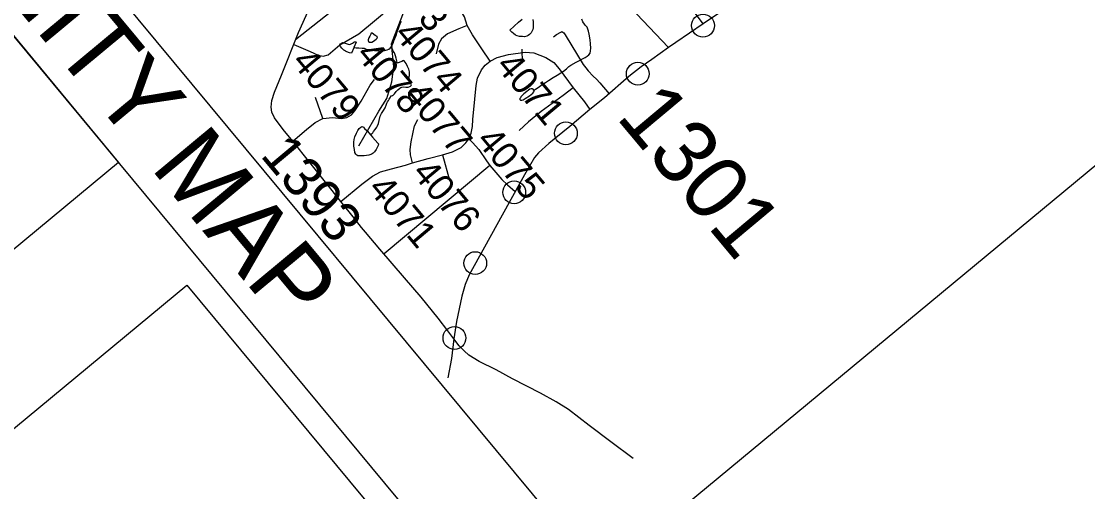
# Model space of a CAD drawing. Extents: x 2054826 to 2060231, y 685508 to 690809.
# Drawn here: x 2058521.5 to 2058951.1, y 689254.7 to 689444.4 of the extents above; entities that cross this region are included whole.
import ezdxf

# ---------------------------------------------------------------- set-up
doc = ezdxf.new("R2010")
doc.units = 0
for name, color, linetype in [('Default', 7, 'Continuous'), ('Old_Level_11', 7, 'Continuous'), ('Old_Level_21', 7, 'Continuous'), ('Old_Level_32', 7, 'Continuous'), ('Old_Level_35', 7, 'Continuous'), ('Old_Level_59', 7, 'Continuous'), ('Old_Level_62', 7, 'Continuous'), ('Old_Level_8', 7, 'Continuous')]:
    doc.layers.add(name, color=color, linetype=linetype)

msp = doc.modelspace()

# ---------------------------------------------------------------- linework, layer by layer
at = {"layer": 'Default'}
for p, q in [((2058363.32, 689625.52), (2058560.72, 689387.48)), ((2058560.72, 689387.48), (2058500.46, 689337.51))]:
    msp.add_line(p, q, dxfattribs=at)
msp.add_lwpolyline([(2058776.37, 689968.05), (2059134.67, 689535.97), (2058721.62, 689193.45), (2058363.32, 689625.52)], close=True, dxfattribs=at)
for centre in [(2058796.12, 689442.62), (2058769.86, 689423.23), (2058740.89, 689399.2), (2058720.08, 689375.4), (2058704.38, 689346.88), (2058696.01, 689316.7)]:
    msp.add_circle(centre, 4.59, dxfattribs=at)
at = {"layer": 'Old_Level_21'}
msp.add_line((2058396.35, 689652.92), (2058754.65, 689220.85), dxfattribs=at)
msp.add_lwpolyline([(2058588.27, 689338), (2059498.4, 688240.46), (2058988.43, 687817.56), (2058078.29, 688915.11)], close=True, dxfattribs=at)
at = {"layer": 'Old_Level_32'}
for p, q in [((2058642.98, 689405.21), (2058640.1, 689413.7)), ((2058691.15, 689390.54), (2058694, 689380.33))]:
    msp.add_line(p, q, dxfattribs=at)
for points in [[(2058623.47, 689405.45), (2058622.51, 689407.72), (2058622.25, 689409.71), (2058622.42, 689412.39), (2058623.56, 689415.82), (2058626.32, 689422.6), (2058633.19, 689439.78), (2058639.88, 689454.86), (2058642.73, 689462.33), (2058644.57, 689467.01), (2058645.65, 689471.4), (2058646.84, 689478.34), (2058647.37, 689483.86), (2058648.12, 689488.16), (2058649.2, 689492.55), (2058653.05, 689504.79), (2058654.38, 689509.38)], [(2058782.21, 689433.75), (2058764.28, 689452.71), (2058757.84, 689460.49), (2058755.43, 689463.58), (2058754.43, 689465.56), (2058753.73, 689467.78), (2058753.31, 689471.05), (2058753.55, 689473.72), (2058754.46, 689476.97), (2058756.27, 689481.12), (2058757.78, 689484.85), (2058758.53, 689487.3), (2058758.67, 689489.22), (2058758.52, 689491.56), (2058757.42, 689494.61), (2058756.92, 689495.64)], [(2058796.17, 689443.35), (2058793.53, 689447.03), (2058791.73, 689449.27), (2058788.76, 689451.86), (2058785.36, 689454.57), (2058782.34, 689457.46), (2058779.99, 689460.51), (2058778.6, 689464.44), (2058777.91, 689469.35), (2058777.15, 689476.78)], [(2058825.7, 689475.43), (2058824.91, 689472.75), (2058823.36, 689467.6), (2058821.22, 689463.57), (2058818.07, 689459.37), (2058815.24, 689456.59), (2058810.85, 689453.12), (2058805.32, 689449.45), (2058799.91, 689445.85), (2058796.17, 689443.35)], [(2058701.16, 689442.68), (2058700.09, 689446.13), (2058698.89, 689448.2), (2058697.15, 689449.48), (2058694.2, 689451.16), (2058691.65, 689453.09), (2058687.93, 689457.27)], [(2058701.16, 689442.68), (2058697.78, 689441.29), (2058693.23, 689439.32), (2058690.78, 689437.29), (2058689.61, 689435.1), (2058688.65, 689431.29)], [(2058710.41, 689428.35), (2058707.02, 689433.27), (2058703.34, 689438.88), (2058701.16, 689442.68)], [(2058796.17, 689443.35), (2058785.21, 689435.86), (2058782.21, 689433.75)], [(2058782.21, 689433.75), (2058775.48, 689429.02), (2058771.23, 689425.94), (2058766.23, 689422.08), (2058756.44, 689413.47), (2058750.56, 689408.82)], [(2058710.41, 689428.35), (2058713.27, 689429.72), (2058717.79, 689430.96), (2058724.44, 689431.97), (2058728, 689431.6), (2058732.84, 689429.76), (2058736.06, 689427.71), (2058738.2, 689425.15), (2058743.86, 689417.59)], [(2058701.83, 689396.92), (2058702.7, 689399.33), (2058703.29, 689401.94), (2058703.48, 689404.84), (2058704.25, 689412.95), (2058704.73, 689418.46), (2058705.31, 689421.49), (2058706.85, 689424.84), (2058708.4, 689426.63), (2058710.41, 689428.35)], [(2058642.98, 689405.21), (2058646.87, 689405.53), (2058650.46, 689405.15), (2058652.72, 689405.57), (2058654.52, 689406.61), (2058655.91, 689408.31), (2058658.37, 689412.17), (2058662.03, 689418.67), (2058663.83, 689420.85)], [(2058743.86, 689417.59), (2058739.86, 689414.42), (2058730.99, 689407.98), (2058725.88, 689403.89), (2058722.12, 689400.39)], [(2058743.86, 689417.59), (2058748.33, 689411.85), (2058750.56, 689408.82)], [(2058750.56, 689408.82), (2058742.49, 689401.99), (2058734.05, 689395.04), (2058729.86, 689391.33), (2058728.2, 689389.48), (2058724.17, 689382.46), (2058718.11, 689371.38), (2058708.07, 689353.31), (2058701.98, 689342.11), (2058700.29, 689338.22), (2058698.93, 689333.6), (2058696.83, 689323.32), (2058695.8, 689316.39)], [(2058630.92, 689396.1), (2058627.08, 689400.77), (2058623.47, 689405.45)], [(2058630.92, 689396.1), (2058636.35, 689400.74), (2058639.92, 689403.52), (2058642.98, 689405.21)], [(2058679.14, 689387.27), (2058678.34, 689390.54), (2058678.17, 689392.74), (2058678.58, 689395.76), (2058679.92, 689402.25), (2058681.3, 689404.8)], [(2058650.29, 689371.78), (2058646.23, 689376.88), (2058637.76, 689387.44), (2058630.92, 689396.1)], [(2058691.15, 689390.54), (2058695.23, 689391.78), (2058698.67, 689393.54), (2058700.62, 689395.41), (2058701.83, 689396.92)], [(2058701.83, 689396.92), (2058703.29, 689395.54), (2058705.8, 689392.66), (2058708.93, 689388.12), (2058710.33, 689386.19)], [(2058679.14, 689387.27), (2058685.42, 689389.08), (2058691.15, 689390.54)], [(2058650.29, 689371.78), (2058658.66, 689378.71), (2058663.02, 689381.89), (2058666.27, 689383.61), (2058670.67, 689384.87), (2058676.33, 689386.39), (2058679.14, 689387.27)], [(2058660.24, 689359.38), (2058658.61, 689361.22), (2058655.69, 689364.93), (2058650.29, 689371.78)], [(2058695.8, 689316.39), (2058693.29, 689319.6), (2058689.4, 689324.74), (2058682.54, 689333.11), (2058675.87, 689340.96), (2058666.01, 689352.51), (2058660.24, 689359.38)], [(2058695.8, 689316.39), (2058694.8, 689308.46), (2058693.34, 689300.63)], [(2058741.98, 689287.86), (2058736.93, 689291.02), (2058730.64, 689294.52), (2058719.36, 689300.26), (2058712.8, 689303.86), (2058705.97, 689307.24), (2058701.86, 689309.82), (2058699.88, 689311.48), (2058697.94, 689313.56), (2058695.8, 689316.39)], [(2058767.94, 689268.1), (2058758.97, 689274.86), (2058750.24, 689281.46), (2058741.98, 689287.86)]]:
    msp.add_lwpolyline(points, dxfattribs=at)
at = {"layer": 'Old_Level_35'}
for p, q in [((2058668.48, 689465.84), (2058632.05, 689436.93)), ((2058723.19, 689433.13), (2058723.23, 689427.78)), ((2058710.33, 689386.19), (2058667.66, 689350.58))]:
    msp.add_line(p, q, dxfattribs=at)
for points in [[(2058631.3, 689435.05), (2058637.84, 689432.16), (2058641.06, 689430.76), (2058643.15, 689430.28), (2058645.17, 689430.88), (2058649.86, 689434.93), (2058657.5, 689439.33), (2058670.89, 689450.41)], [(2058735.91, 689438.13), (2058737.17, 689439.05), (2058738.8, 689440.03), (2058739.24, 689440.21), (2058739.73, 689440.02), (2058740.02, 689439.76), (2058740.58, 689438.96), (2058747.9, 689426.92), (2058748.91, 689425.56), (2058749.89, 689424.35), (2058751.92, 689422.23), (2058753.22, 689421.02), (2058754.59, 689419.62), (2058758.35, 689415.15)], [(2058710.33, 689386.19), (2058715.15, 689380.54), (2058717.32, 689378.4), (2058720.5, 689375.75)]]:
    msp.add_lwpolyline(points, dxfattribs=at)
at = {"layer": 'Old_Level_59'}
msp.add_lwpolyline([(2058657.45, 689394.18), (2058665.56, 689408.08), (2058668.72, 689413.18), (2058670.84, 689419.9), (2058671.54, 689426.18), (2058670.65, 689435.3), (2058675.87, 689448.9), (2058677.76, 689461.15)], dxfattribs=at)
at = {"layer": 'Old_Level_62'}
for points in [[(2058670.84, 689434.29), (2058670.89, 689434.43), (2058670.97, 689434.75), (2058671.26, 689435.5), (2058671.63, 689436.47), (2058671.99, 689437.37), (2058672.44, 689438.35), (2058672.72, 689439.01), (2058672.74, 689439.71), (2058672.87, 689440.16), (2058673.06, 689440.55), (2058673.16, 689440.83), (2058673.49, 689441.44), (2058673.7, 689442.21), (2058674.11, 689443.33), (2058674.63, 689444.44)], [(2058727.59, 689445.03), (2058727.71, 689444.18), (2058727.69, 689442.98), (2058727.68, 689441.79), (2058727.53, 689441.06), (2058727.23, 689440.31), (2058726.9, 689439.69), (2058726.25, 689439.06), (2058725.71, 689438.69), (2058725.12, 689438.38), (2058724.27, 689438.16), (2058723.4, 689438.19), (2058722.25, 689438.26), (2058721.21, 689438.48), (2058720.58, 689438.81), (2058719.76, 689439.39), (2058719.09, 689440), (2058718.7, 689440.36), (2058718.36, 689440.76), (2058721.87, 689443.96), (2058723.31, 689445.17)], [(2058728.01, 689416.63), (2058728.32, 689416.78), (2058728.65, 689416.98), (2058729.34, 689417.38), (2058730.31, 689418.04), (2058731.4, 689418.86), (2058732.62, 689419.64), (2058733.88, 689420.45), (2058735.71, 689421.71), (2058737.41, 689422.71), (2058738.86, 689423.52), (2058739.94, 689424.25), (2058741.13, 689425.26), (2058741.75, 689425.85), (2058742.04, 689426.1), (2058742.87, 689426.64), (2058745, 689427.83), (2058746.6, 689428.65), (2058747.61, 689429.17), (2058748.68, 689429.72), (2058749.51, 689430.25), (2058750.2, 689430.84), (2058750.63, 689431.53), (2058750.84, 689432.4), (2058750.93, 689433.49), (2058750.81, 689435.26), (2058750.63, 689436.89), (2058750.27, 689439.12), (2058750.01, 689440.35), (2058749.76, 689441.15), (2058749.41, 689441.97), (2058748.79, 689442.71), (2058748.33, 689443.17), (2058747.72, 689444.1), (2058747.27, 689445.25)], [(2058664.12, 689438.67), (2058662.82, 689439.61), (2058662.52, 689439.54), (2058662.31, 689439.18), (2058661.93, 689438.43), (2058661.49, 689437.65), (2058661.24, 689436.93), (2058661.2, 689436.56), (2058661.37, 689436.26), (2058661.76, 689436), (2058662.27, 689435.92), (2058662.78, 689436.01), (2058663.46, 689436.32), (2058664.49, 689437.1), (2058664.94, 689437.57), (2058665.02, 689437.99), (2058664.9, 689438.14), (2058664.82, 689438.22), (2058664.12, 689438.67)], [(2058655.53, 689433.83), (2058655.43, 689433.65), (2058654.59, 689431.51), (2058653.68, 689431.68), (2058652.65, 689431.99), (2058652.08, 689432.28), (2058651.77, 689432.53), (2058651.52, 689432.75), (2058650.71, 689433.5), (2058650.12, 689434.2), (2058649.88, 689434.69), (2058649.86, 689434.92), (2058650.02, 689435.24), (2058650.32, 689435.47), (2058650.95, 689435.75), (2058651.45, 689435.74), (2058652.44, 689435.47), (2058653.16, 689435.14), (2058653.6, 689435.02), (2058654.12, 689435.1), (2058654.9, 689435.5), (2058655.34, 689435.88), (2058655.49, 689436), (2058655.73, 689436.11), (2058656.05, 689436.14), (2058656.28, 689436.07), (2058656.41, 689435.92), (2058655.53, 689433.83)], [(2058655.53, 689433.83), (2058655.85, 689433.75), (2058656.4, 689433.7), (2058657.49, 689433.61), (2058658.87, 689433.58), (2058659.65, 689433.47), (2058660.5, 689433.16), (2058661.45, 689432.95), (2058662.63, 689432.76), (2058663.86, 689432.59), (2058665.28, 689432.51), (2058666.35, 689432.57), (2058667.32, 689432.62), (2058667.83, 689432.62), (2058668.36, 689432.7), (2058668.96, 689432.89), (2058669.59, 689433.16), (2058670.13, 689433.53), (2058670.84, 689434.29)], [(2058672.92, 689427.47), (2058672.93, 689427.65), (2058672.78, 689428.44), (2058672.54, 689429.52), (2058672.3, 689430.43), (2058671.9, 689431.61), (2058671.36, 689432.35), (2058671.01, 689433.18), (2058670.88, 689433.65), (2058670.85, 689433.87), (2058670.88, 689434.15), (2058670.84, 689434.29)], [(2058670.39, 689414.32), (2058670.62, 689414.25), (2058670.9, 689414.32), (2058671.08, 689414.39), (2058671.38, 689414.55), (2058671.85, 689415.11), (2058672.51, 689416.02), (2058673.24, 689416.78), (2058674.03, 689417.45), (2058674.42, 689417.7), (2058674.83, 689417.8), (2058675.59, 689417.91), (2058676.37, 689417.8), (2058676.92, 689417.76), (2058677.33, 689417.76), (2058678.05, 689418.03), (2058678.29, 689418.23), (2058678.55, 689418.54), (2058678.65, 689418.72), (2058678.64, 689419.04), (2058678.37, 689419.66), (2058677.92, 689420.81), (2058677.79, 689421.37), (2058677.71, 689421.56), (2058677.68, 689421.8), (2058677.75, 689422.11), (2058677.88, 689422.47), (2058677.96, 689422.87), (2058677.92, 689424.04), (2058677.65, 689425.06), (2058677.13, 689426.09), (2058676.51, 689427.34), (2058676.13, 689427.89), (2058675.81, 689428.36), (2058675.68, 689428.43), (2058675.45, 689428.5), (2058674.78, 689428.18), (2058672.92, 689427.47)], [(2058728.01, 689416.63), (2058727.73, 689416.96), (2058727.42, 689417.13), (2058726.86, 689417.1), (2058726.39, 689416.95), (2058725.9, 689416.61), (2058725.15, 689416.08), (2058723.97, 689415.08), (2058723.21, 689414.37), (2058722.75, 689413.89), (2058722.55, 689413.55), (2058722.41, 689413.19), (2058722.35, 689412.97), (2058722.38, 689412.82), (2058722.51, 689412.68), (2058722.68, 689412.57), (2058723.14, 689412.52), (2058723.66, 689412.72), (2058724.55, 689413.27), (2058726.2, 689414.34), (2058726.95, 689414.87), (2058727.54, 689415.37), (2058727.96, 689415.89), (2058728.12, 689416.2), (2058728.11, 689416.52), (2058728.01, 689416.63)], [(2058662.27, 689398.42), (2058662.68, 689398.93), (2058663.09, 689399.46), (2058663.46, 689399.92), (2058664.09, 689400.8), (2058664.68, 689401.62), (2058664.95, 689402.19), (2058665.36, 689403.22), (2058665.65, 689404.38), (2058666.12, 689406.07), (2058666.63, 689407.16), (2058667.43, 689408.43), (2058668.13, 689409.53), (2058668.53, 689410.56), (2058668.84, 689411.4), (2058669.03, 689411.89), (2058669.39, 689412.37), (2058669.77, 689412.94), (2058670.21, 689413.82), (2058670.39, 689414.32)], [(2058662.27, 689398.42), (2058663.02, 689397.61), (2058665.12, 689395.21), (2058665.47, 689394.91), (2058665.28, 689394.32), (2058664.49, 689392.64), (2058663.85, 689391.68), (2058663.31, 689391.22), (2058662.91, 689390.97), (2058662.39, 689390.71), (2058661.53, 689390.41), (2058660.59, 689390.2), (2058659.61, 689390.15), (2058658.4, 689390.08), (2058657.53, 689390.11), (2058657.13, 689390.19), (2058656.72, 689390.46), (2058656.31, 689390.86), (2058655.95, 689391.49), (2058655.72, 689392.67), (2058655.52, 689394.02), (2058655.53, 689395.64), (2058655.6, 689396.65), (2058655.9, 689397.82), (2058656.49, 689399.33), (2058657.05, 689400.39), (2058657.57, 689401.09), (2058658.27, 689401.67), (2058658.65, 689401.92), (2058659.05, 689401.84), (2058659.33, 689401.71), (2058659.84, 689401.21), (2058660.8, 689400.16), (2058662.27, 689398.42)]]:
    msp.add_lwpolyline(points, dxfattribs=at)

# ---------------------------------------------------------------- texts
at = {"layer": 'Old_Level_11'}
msp.add_text('VICINITY MAP', height=29.6875, rotation=309.7424, dxfattribs=at).set_placement((2058458.94, 689522.81))
at = {"layer": 'Old_Level_8'}
for s, height, p in [('4073', 10.796, (2058665.56, 689463.91)), ('4074', 10.796, (2058671.31, 689439)), ('4078', 10.796, (2058655.97, 689430.76)), ('4079', 10.796, (2058630.04, 689427.82)), ('4071', 10.796, (2058712.3, 689426.24)), ('4077', 10.796, (2058675.12, 689414.43)), ('1301', 25.74, (2058760.75, 689405.68)), ('4075', 10.796, (2058704.41, 689396.1)), ('1393', 15.869, (2058617.49, 689390.2)), ('4076', 10.796, (2058678.53, 689383.08)), ('4071', 10.796, (2058660.75, 689376.7))]:
    msp.add_text(s, height=height, rotation=309.9093, dxfattribs=at).set_placement(p)

doc.saveas('drawing.dxf')
